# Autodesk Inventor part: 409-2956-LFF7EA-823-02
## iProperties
Created: 2010-11
Part Number: 409-2956-LFF7EA-823-02
Material: 3/8" OD TUBE - SS
Document SubType Name: Modeling
Designer: S. Boerckel
Engineer: Steve Boerckel
Mass: 376.34 g
Surface Area: 815.594 cm^2
Volume: 46.5768 cm^3
Density: 8.08 g/cm^3
Description: PRESSURE DIFF TUBE
Length: 56.262 in
Author: S. Boerckel
Revision Number: 0
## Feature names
1. Sweep4
